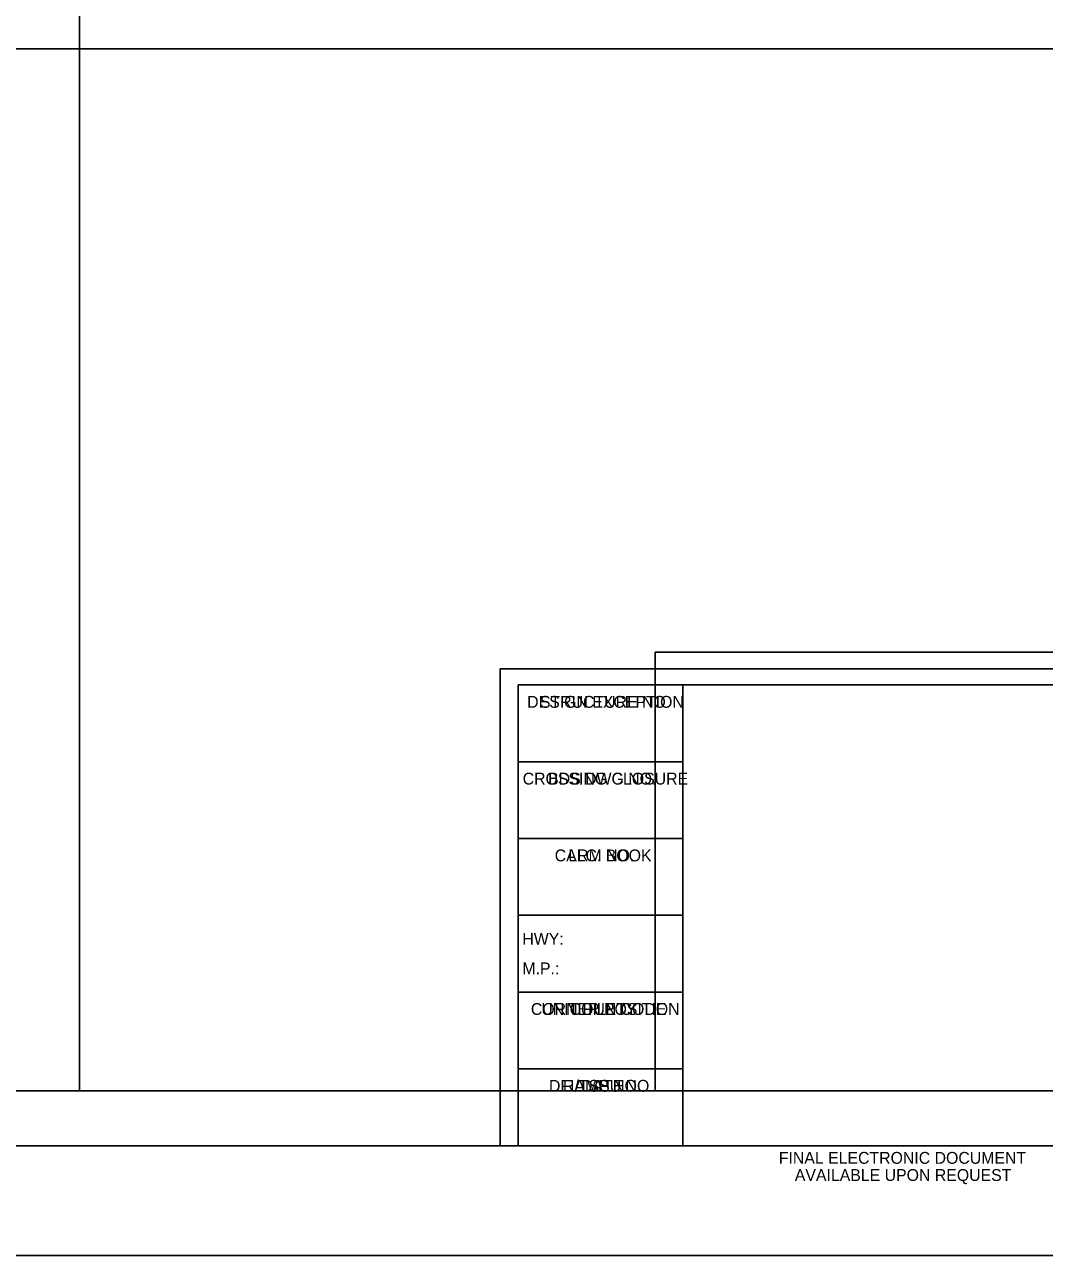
# Model space of a CAD drawing. Extents: x 0 to 1.42, y 0 to 0.92.
# Drawn here: x 0.7083 to 1.0957, y 0 to 0.4675 of the extents above; entities that cross this region are included whole.
import ezdxf

# ---------------------------------------------------------------- set-up
doc = ezdxf.new("R2010")
doc.units = 0
for name, color, linetype in [('#plot_layout', 7, 'Continuous'), ('#plot_shape', 7, 'Continuous'), ('P_ODOT_PLAN_Border', 7, 'Continuous'), ('P_ODOT_PLAN_General', 7, 'Continuous'), ('P_ODOT_PLAN_TBBDSDwg', 7, 'Continuous'), ('P_ODOT_PLAN_TBBgStrInfo', 7, 'Continuous'), ('P_ODOT_PLAN_TBdfiTSSU', 7, 'Continuous'), ('P_ODOT_PLAN_TBlock', 7, 'Continuous'), ('P_ODOT_PLAN_TBStrBoxes', 7, 'Continuous'), ('P_RDWY_PLAN_Detail', 7, 'Continuous')]:
    doc.layers.add(name, color=color, linetype=linetype)

msp = doc.modelspace()

# ---------------------------------------------------------------- linework, layer by layer
at = {"layer": '#plot_layout'}
msp.add_line((0.72914, 0.85413), (0.72918, 0.0625), dxfattribs=at)
msp.add_lwpolyline([(0.08333, 0.45832), (1.37503, 0.45832), (1.37503, 0.0625), (0.08333, 0.0625)], close=True, dxfattribs=at)
at = {"layer": '#plot_shape'}
msp.add_lwpolyline([(0, 0), (1.41667, 0), (1.41667, 0.91667), (0, 0.91667)], close=True, dxfattribs=at)
at = {"layer": 'P_ODOT_PLAN_Border'}
for p, q in [((0.94789, 0.0625), (0.94789, 0.22916)), ((0.94789, 0.22916), (1.37495, 0.22916)), ((0.08333, 0.0625), (0.94789, 0.0625))]:
    msp.add_line(p, q, dxfattribs=at)
msp.add_lwpolyline([(0.0625, 0.04167), (1.39583, 0.04167), (1.39583, 0.875), (0.0625, 0.875)], close=True, dxfattribs=at)
at = {"layer": 'P_ODOT_PLAN_General'}
msp.add_lwpolyline([(1.39587, 0.04167), (0.88904, 0.04167), (0.88904, 0.22282), (1.39587, 0.22282)], close=True, dxfattribs=at)
at = {"layer": 'P_ODOT_PLAN_TBBgStrInfo'}
for points in [[(0.89587, 0.12917), (0.95837, 0.12917), (0.95837, 0.1), (0.89587, 0.1)], [(0.89587, 0.1), (0.95837, 0.1), (0.95837, 0.07083), (0.89587, 0.07083)], [(0.89587, 0.07083), (0.95837, 0.07083), (0.95837, 0.04167), (0.89587, 0.04167)]]:
    msp.add_lwpolyline(points, close=True, dxfattribs=at)
at = {"layer": 'P_ODOT_PLAN_TBdfiTSSU'}
for p, q in [((0.89587, 0.12917), (0.95837, 0.12917)), ((0.89587, 0.1), (0.95837, 0.1)), ((0.89587, 0.07083), (0.95837, 0.07083))]:
    msp.add_line(p, q, dxfattribs=at)
for points in [[(0.89587, 0.12917), (0.95837, 0.12917), (0.95837, 0.1), (0.89587, 0.1)], [(0.89587, 0.1), (0.95837, 0.1), (0.95837, 0.07083), (0.89587, 0.07083)], [(0.89587, 0.07083), (0.95837, 0.07083), (0.95837, 0.04167), (0.89587, 0.04167)]]:
    msp.add_lwpolyline(points, close=True, dxfattribs=at)
at = {"layer": 'P_ODOT_PLAN_TBlock'}
msp.add_line((1.03962, 0.12917), (1.03962, 0.12917), dxfattribs=at)
msp.add_lwpolyline([(0.95837, 0.04167), (1.39587, 0.04167), (1.39587, 0.21667), (0.95837, 0.21667)], close=True, dxfattribs=at)
at = {"layer": 'P_ODOT_PLAN_TBStrBoxes'}
for p, q in [((0.89587, 0.1875), (0.95837, 0.1875)), ((0.89587, 0.15833), (0.95837, 0.15833)), ((0.89587, 0.12917), (0.95837, 0.12917)), ((0.89587, 0.1), (0.95837, 0.1)), ((0.89587, 0.07083), (0.95837, 0.07083))]:
    msp.add_line(p, q, dxfattribs=at)
msp.add_lwpolyline([(0.89587, 0.04167), (0.95837, 0.04167), (0.95837, 0.21667), (0.89587, 0.21667)], close=True, dxfattribs=at)

# ---------------------------------------------------------------- texts
at = {"layer": 'P_ODOT_PLAN_TBBDSDwg'}
for s, p in [('STRUCTURE NO.', (0.90409, 0.208)), ('BDS DWG NO.', (0.9072, 0.17883)), ('CALC. BOOK', (0.9097, 0.14967))]:
    msp.add_text(s, height=0.0045, dxfattribs=at).set_placement(p)
at = {"layer": 'P_ODOT_PLAN_TBBgStrInfo'}
for s, p in [('HWY:', (0.89741, 0.118)), ('M.P.:', (0.89741, 0.10675)), ('COUNTY', (0.91538, 0.09133)), ('DATE', (0.91975, 0.06215))]:
    msp.add_text(s, height=0.0045, dxfattribs=at).set_placement(p)
at = {"layer": 'P_ODOT_PLAN_TBdfiTSSU'}
for s, p in [('HWY:', (0.89741, 0.118)), ('M.P.:', (0.89741, 0.10675)), ('UNIT FILE CODE', (0.90462, 0.09133)), ('DFI/TSSU NO.', (0.90752, 0.06215))]:
    msp.add_text(s, height=0.0045, dxfattribs=at).set_placement(p)
at = {"layer": 'P_ODOT_PLAN_TBlock'}
for s, p in [('FINAL ELECTRONIC DOCUMENT', (0.99482, 0.03479)), ('AVAILABLE UPON REQUEST', (1.00091, 0.02827))]:
    msp.add_text(s, height=0.0045, dxfattribs=at).set_placement(p)
at = {"layer": 'P_RDWY_PLAN_Detail'}
for s, p in [('DESIGN EXCEPTION', (0.89923, 0.208)), ('CROSSING CLOSURE', (0.89753, 0.17883)), ('LRM NO.', (0.91486, 0.14967)), ('HWY:', (0.89741, 0.118)), ('M.P.:', (0.89741, 0.10675)), ('CORNER POSITION', (0.90065, 0.09133)), ('RAMP NO.', (0.91282, 0.06217))]:
    msp.add_text(s, height=0.0045, dxfattribs=at).set_placement(p)

doc.saveas('drawing.dxf')
